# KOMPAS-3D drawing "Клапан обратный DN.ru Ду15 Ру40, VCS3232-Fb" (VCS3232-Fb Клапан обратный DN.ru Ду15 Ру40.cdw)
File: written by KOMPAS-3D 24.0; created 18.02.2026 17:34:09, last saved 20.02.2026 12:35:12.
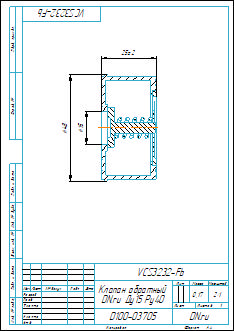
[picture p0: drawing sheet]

Document properties: a: 1; Артикул: D100-03705; Автор: R2D2; Форматы листов документа: A4; Полное имя файла: VCS3232-Fb Клапан обратный DN.ru Ду15 Ру40.m3d; Масса: 0.17; Наименование: Клапан обратный DN.ru Ду15 Ру40; Количество листов документа: 1; Примечание: D100-03705

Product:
- Body: Тело 1  | qty 1
    Масса: 0.085135
- Body: Тело 2  | qty 1
    Масса: 0.016987
- Part/product: Клапан обратный DN.ru Ду15 Ру40  | designation VCS3232-Fb
    Масса: 0.17
    Форматы листов документа: A4
    Примечание: D100-03705
    additional columns: 1; D100-03705

Views: Вид 1, Местный разрез 2, Справа
Referenced files in E:\Работа\Зайцев\VCS3232-Fb Клапан обратный DN.ru Ду15-100\DN15\: VCS3232-Fb Клапан обратный DN.ru Ду15 Ру40.m3d
Referenced files in E:\Работа\Зайцев\Для компаса\: чертеж DN.ru.cdt
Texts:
  VCS3232-Fb
  чертеж DN.ru.cdt
  Клапан обратный
  DN.ru Ду15 Ру40
  prop
  Клапан обратный DN.ru Ду15 Ру40
  VCS3232-Fb Клапан обратный DN.ru Ду15 Ру40
Dimensions and other numbers on the sheet: 0; 3; 2; 4; 48; 15; 25±2; 6; 2:1; 1; 0,17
